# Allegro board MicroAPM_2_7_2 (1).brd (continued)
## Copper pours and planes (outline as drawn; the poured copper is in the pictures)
3.3V on BOTTOM (solid shape): 26.42,11.81 26.42,10.57 26.31,10.47 26.31,8.89 25.78,8.36 25.78,7.49 25.6,7.32 25.6,6.15 25.5,6.05 24.49,6.05 24.41,6.12 24.41,8.51 24.41,9.04 24.71,9.35 25.76,9.35 25.76,11.35 25.7,11.35 25.7,11.6 25.65,11.64 25.65,11.94 26.29,11.94
5V on TOP (solid shape): 26.8,3.81 26.8,2.29 26.67,2.16 25.91,2.16 25.78,2.29 25.78,3.81 25.91,3.94 26.67,3.94
5V on BOTTOM (solid shape): 1.78,28.45 1.78,27.05 1.27,26.54 1.27,25.91 1.14,25.78 0.76,25.78 0.64,25.91 0.64,28.45 0.76,28.57 1.65,28.57
5V on ART03 (solid shape): outline of 173 points within 0.64,2.41 26.8,27.81
GND on TOP (solid shape): 17.45,20.6 17.45,17.68 17.2,17.42 14.27,17.42 14.27,20.73 17.32,20.73
GND on TOP (solid shape): 25.53,21.59 25.53,19.18 25.4,19.05 22.99,19.05 22.9,19.13 22.9,21.63 22.94,21.67 25.44,21.67
GND on TOP (solid shape): 25.27,27.56 25.27,27.14 25.07,26.93 25.07,25.15 24.77,25.15 23.37,26.54 23.37,27.3 23.88,27.81 25.02,27.81
GND on TOP (solid shape): 17.65,28.19 18.29,28.19 18.89,27.6 18.96,27.47 19.09,27.39 20.37,26.11 20.37,26.03 20.7,25.69 20.7,24.64 20.57,24.51 16.38,24.51 16.26,24.64 16.26,24.89 16.52,25.16 16.52,28.33 16.64,28.45 17.4,28.45
GND on TOP (solid shape): 10.03,12.19 10.41,12.19 10.46,12.14 10.46,10.49 10.54,10.41 10.54,9.91 10.41,9.78 9.02,9.78 8.89,9.91 8.89,10.54 9.84,10.54 9.84,11.03 9.98,11.17 9.98,11.87 9.71,12.14 9.44,12.14 9.4,12.1 7.66,12.1 7.47,11.91 7.47,11.64 7.66,11.44 7.94,11.44 7.94,10.58 7.85,10.49 7.85,9.93 7.82,9.91 6.22,9.91 6.12,10.01 6.12,10.82 6.22,10.92 6.6,10.92 6.99,11.3 6.99,11.47 7.19,11.67 7.19,13.07 7.38,13.26 8.97,13.26
GND on TOP (solid shape): 16.18,8.71 16.18,8.63 16.63,8.18 17.41,8.18 17.99,8.76 19.94,8.76 20.19,9.02 22.58,9.02 22.66,8.92 22.76,8.86 22.77,8.85 23.11,8.51 23.11,7.11 22.99,6.99 17.91,6.99 17.78,7.11 16.98,7.11 16.92,7.17 16.65,7.17 16.59,7.11 16.22,7.11 16.14,7.19 15.87,7.19 15.79,7.11 14.98,7.11 14.54,7.56 13.27,7.56 13.21,7.62 13.21,8.3 13.41,8.5 13.41,9.09 13.46,9.14 15.75,9.14
GND on TOP (solid shape): outline of 776 points within 0.53,0.56 34.42,34.39
GND on BOTTOM (solid shape): 15.03,9.26 15.8,8.5 15.8,7.92 15.75,7.87 13.84,7.87 13.59,8.13 13.59,9.02 13.84,9.27 15.03,9.27
GND on BOTTOM (solid shape): 13.59,24.21 13.59,23.63 12.56,22.61 12.45,22.61 12.37,22.68 12.37,23.61 13.04,24.28 13.51,24.28
GND on BOTTOM (solid shape): 12.95,26.92 12.95,26.67 12.7,26.42 11.68,26.42 11.56,26.29 11.56,25.78 11.94,25.4 12.18,25.4 12.24,25.34 12.24,24.9 12.08,24.74 10.69,24.74 10.41,25.02 10.41,25.95 10.49,26.03 10.49,26.3 10.41,26.38 10.41,26.92 10.54,27.05 12.83,27.05
GND on BOTTOM (solid shape): 26.03,23.02 26.13,23.02 26.29,22.86 26.29,21.72 26.16,21.59 25.91,21.59 25.53,21.97 25.36,21.97 25.03,22.3 21.32,22.3 20.6,21.59 20.6,19.72 20.45,19.56 19.68,19.56 19.43,19.81 19.43,20.02 19.48,20.19 19.43,20.36 19.43,20.87 20.02,21.45 20.02,21.85 21.02,22.85 21.02,22.92 21.21,23.11 25.93,23.11
GND on BOTTOM (solid shape): outline of 86 points within 22.23,12.7 26.36,21.59
GND on BOTTOM (solid shape): outline of 101 points within 8.76,6.6 10.41,10.54
GND on BOTTOM (solid shape): outline of 492 points within 0.64,0.64 34.29,20.57
GND on BOTTOM (solid shape): outline of 527 points within 0.6,24.38 34.42,34.37
GND on ART02 (solid shape): outline of 7673 points within 0.51,0.51 34.49,34.49
GND on ART03 (solid shape): 18.48,27.81 18.48,27.17 19.36,26.29 22.48,26.29 22.73,26.04 22.73,24.89 21.21,23.37 18.92,23.37 18.86,23.3 18.79,23.3 18.66,23.18 13.64,23.18 13.57,23.11 13.39,23.11 13.01,22.73 12.64,22.73 12.45,22.93 12.45,25.02 12.7,25.27 14.86,25.27 17.53,27.94 18.35,27.94
GND on ART03 (solid shape): 1.65,15.75 1.65,7.24 5.46,3.43 22.23,3.43 23.62,2.03 26.95,2.03 27.18,2.26 27.18,4.19 30.99,8 34.29,8 34.42,7.87 34.42,1.78 33.27,0.64 1.65,0.64 0.61,1.68 0.61,15.98 0.76,16.13 1.27,16.13
GND on ART03 (solid shape): outline of 113 points within 22.73,18.16 28.96,26.67
GND on ART03 (solid shape): outline of 204 points within 0.6,28.26 34.42,34.42
VCC on TOP (solid shape): 28.19,10.41 28.19,9.91 28.45,9.65 29.97,9.65 30.1,9.53 30.1,8.89 29.97,8.76 28.19,8.76 27.69,8.26 27.69,7.49 27.43,7.24 23.75,7.24 23.5,7.49 23.5,8.97 23.37,9.09 23.37,10.03 24.05,10.72 27.89,10.72
VCC on BOTTOM (solid shape): 5.84,24.89 5.84,22.82 5.64,22.62 5.64,22.23 4.36,20.95 2.41,20.95 2.16,21.21 2.16,22.1 2.29,22.22 3.43,22.22 3.94,22.73 3.94,24.89 4.06,25.02 5.71,25.02
VCC on BOTTOM (solid shape): 29.08,10.03 29.08,9.02 29.84,8.26 29.84,6.35 29.72,6.22 27.18,6.22 27.05,6.35 27.05,6.86 27.18,6.99 28.32,6.99 28.57,7.24 28.57,9.02 28.45,9.14 26.95,9.14 26.7,9.4 26.7,10.31 26.8,10.41 28.7,10.41
VCC on BOTTOM (solid shape): outline of 1179 points within 11.68,7.49 24.51,25.15
VCC on ART03 (solid shape): outline of 1451 points within 2.48,6.16 31.41,28.83
$$$11 on BOTTOM (solid shape): 3.17,25.91 3.17,22.73 3.05,22.61 1.65,22.61 1.65,25.91 1.78,26.04 3.05,26.04
JP_VCC on TOP (solid shape): 7.37,28.57 7.37,27.56 7.24,27.43 6.1,27.43 5.89,27.23 5.89,26.09 5.84,26.04 4.45,26.04 4.32,26.16 4.32,28.45 4.45,28.57 5.33,28.57 5.59,28.83 7.11,28.83
JP_VCC on BOTTOM (solid shape): 7.37,28.57 7.37,27.56 7.24,27.43 6.6,27.43 6.48,27.3 6.48,25.4 5.33,25.4 5.33,28.7 5.46,28.83 7.11,28.83

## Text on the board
BOTTOM: ARTWORK BOTTOM
Board Geometry/Soldermask Bottom: SOLDERMASK BOTTOM
Package Geometry/Pastemask Bottom: PASTEMASK BOTTOM
Ref Des/Silkscreen Bottom: SILKSCREEN BOTTOM
TOP: ARTWORK TOP
Board Geometry/Soldermask Top: SOLDERMASK TOP
Package Geometry/Pastemask Top: PASTEMASK TOP
Ref Des/Silkscreen Top: MicroAPM_2.72 | SILKSCREEN TOP
ART02: ARTWORK LAYER02
ART03: ARTWORK LAYER03
DIMENSION: SINGLE TRACE IMPEDANCE CONTROL | DIFFERENTIAL PAIR IMPEDANCE CONTROL | 1,3,4 | LAYER | 1 | WIDTH (mils) | 6 | 6.5/7.8 | IMPEDANCE (ohm) | 50 | 90 | PRECISION | +/-10% | FREQUENCY (MHZ) | DEFAULT | REMARK | FAB DRAWING
BODY_CENTER: PRIMARY SIDE
ASSEMBLY_BOTTOM: SECONDARY SIDE
User.13: FIGURE | SIZE | 8.0 | 12.0 | 118.0 | 40.0x32.0 | 65.0x33.0 | DRILL CHART: TOP to BOTTOM | ALL UNITS ARE IN MILS | PLATED | QTY | 230 | 48 | 4 | 2
